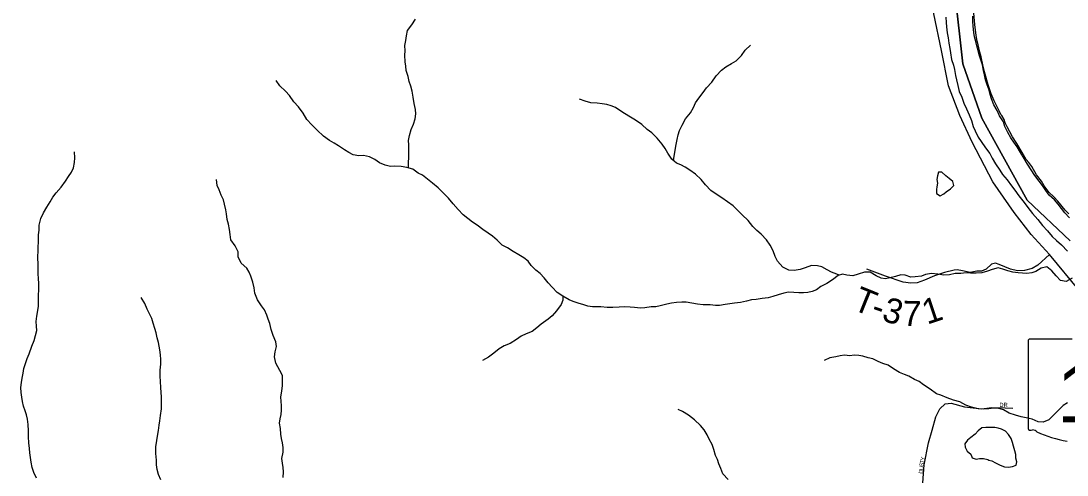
# Model space of a CAD drawing. Extents: x 1624196 to 2029251, y 146837 to 440034.
# Drawn here: x 1809621 to 1822196, y 296635 to 302092 of the extents above; entities that cross this region are included whole.
import ezdxf

# ---------------------------------------------------------------- set-up
doc = ezdxf.new("R2010")
doc.units = 0
for name, color, linetype in [('GM_X_Major_River', 7, 'Continuous'), ('GM_X_Minor_Lake', 7, 'Continuous'), ('GM_X_Minor_River', 7, 'Continuous'), ('GM_X_Section', 7, 'Continuous'), ('GM_X_State_Route', 7, 'Continuous'), ('GM_X_State_Shield', 7, 'Continuous'), ('GM_X_Township', 7, 'Continuous'), ('GM_X_Township_Road', 7, 'Continuous'), ('GM_X_Township_Road_Text', 7, 'Continuous'), ('GM_X_Township_Subdivision', 7, 'Continuous'), ('GM_X_Township_Subdivision_Text', 7, 'Continuous')]:
    doc.layers.add(name, color=color, linetype=linetype)

msp = doc.modelspace()

# ---------------------------------------------------------------- linework, layer by layer
at = {"layer": 'GM_X_Major_River'}
for points in [[(1820738, 302136), (1820741, 302073), (1820745, 302019), (1820754, 301949), (1820766, 301889), (1820776, 301824), (1820785, 301762), (1820795, 301710), (1820806, 301627), (1820832, 301559), (1820844, 301507), (1820855, 301438), (1820865, 301384), (1820881, 301316), (1820900, 301244), (1820930, 301175), (1820956, 301105), (1820987, 301034), (1821017, 300964), (1821045, 300896), (1821068, 300823), (1821090, 300771), (1821125, 300696), (1821161, 300642), (1821215, 300567), (1821267, 300499), (1821294, 300444), (1821336, 300376), (1821388, 300299), (1821420, 300247), (1821475, 300183), (1821529, 300112), (1821569, 300060), (1821617, 299989), (1821678, 299910), (1821724, 299848), (1821778, 299777), (1821846, 299707), (1821899, 299634), (1821959, 299568), (1822017, 299503), (1822067, 299453), (1822129, 299400), (1822202, 299325)], [(1822223, 299727), (1822169, 299785), (1822129, 299839), (1822090, 299892), (1822044, 299944), (1821980, 299999), (1821940, 300055), (1821900, 300114), (1821859, 300166), (1821809, 300233), (1821765, 300301), (1821719, 300372), (1821680, 300438), (1821634, 300509), (1821594, 300577), (1821557, 300636), (1821521, 300688), (1821483, 300750), (1821449, 300823), (1821430, 300879), (1821384, 300952), (1821354, 301016), (1821317, 301083), (1821289, 301157), (1821273, 301209), (1821260, 301259), (1821232, 301334), (1821214, 301386), (1821203, 301444), (1821191, 301497), (1821179, 301563), (1821162, 301613), (1821138, 301684), (1821126, 301736), (1821111, 301794), (1821097, 301844), (1821081, 301901), (1821076, 301953), (1821068, 302027), (1821062, 302087), (1821063, 302148)]]:
    msp.add_lwpolyline(points, dxfattribs=at)
at = {"layer": 'GM_X_Minor_Lake'}
for points in [[(1820666, 300275), (1820652, 300275), (1820638, 300231), (1820632, 300185), (1820637, 300143), (1820631, 300097), (1820625, 300065), (1820627, 300017), (1820671, 299992), (1820713, 300014), (1820744, 300037)], [(1820744, 300037), (1820794, 300076), (1820836, 300116), (1820822, 300162), (1820778, 300197), (1820738, 300231), (1820692, 300273), (1820666, 300275)], [(1821234, 297207), (1821218, 297207), (1821172, 297201), (1821125, 297167), (1821089, 297127), (1821038, 297086), (1820998, 297054), (1820966, 297012), (1820970, 296969), (1820993, 296923), (1821039, 296887), (1821055, 296841), (1821101, 296826), (1821144, 296832), (1821192, 296832), (1821244, 296820), (1821257, 296815)], [(1821257, 296815), (1821290, 296805), (1821336, 296783), (1821392, 296755), (1821442, 296734), (1821492, 296728), (1821539, 296738), (1821583, 296754), (1821593, 296794), (1821581, 296836), (1821580, 296884), (1821566, 296928), (1821552, 296983), (1821540, 297027), (1821524, 297075), (1821491, 297121), (1821455, 297164), (1821409, 297188), (1821366, 297200), (1821326, 297205), (1821286, 297207), (1821234, 297207)], [(1821300, 297207), (1821298, 297207)]]:
    msp.add_lwpolyline(points, dxfattribs=at)
at = {"layer": 'GM_X_Minor_River'}
for points in [[(1814281, 300325), (1814281, 300384), (1814284, 300460), (1814284, 300527), (1814282, 300601), (1814279, 300657), (1814293, 300717), (1814312, 300789), (1814338, 300853), (1814361, 300915), (1814367, 300976), (1814364, 301028), (1814346, 301100), (1814336, 301177), (1814323, 301247), (1814307, 301309), (1814289, 301365), (1814274, 301426), (1814252, 301498), (1814247, 301548), (1814241, 301601), (1814237, 301679), (1814238, 301731), (1814236, 301795), (1814247, 301855), (1814255, 301913), (1814269, 301976), (1814320, 302046), (1814365, 302112)], [(1817466, 300411), (1817471, 300465), (1817485, 300536), (1817494, 300588), (1817508, 300668), (1817519, 300724), (1817535, 300774), (1817568, 300838), (1817608, 300916), (1817669, 300988), (1817704, 301050), (1817730, 301108), (1817771, 301162), (1817823, 301232), (1817862, 301288), (1817924, 301354), (1817979, 301432), (1818040, 301500), (1818092, 301541), (1818163, 301579), (1818217, 301611), (1818282, 301677), (1818328, 301741), (1818389, 301802)], [(1816133, 298784), (1816067, 298828), (1816005, 298893), (1815960, 298943), (1815912, 299006), (1815862, 299058), (1815810, 299095), (1815752, 299153), (1815716, 299204), (1815664, 299244), (1815606, 299283), (1815536, 299321), (1815471, 299364), (1815405, 299398), (1815345, 299459), (1815291, 299507), (1815237, 299540), (1815173, 299586), (1815103, 299637), (1815049, 299675), (1814993, 299718), (1814937, 299762), (1814877, 299825), (1814818, 299893), (1814760, 299964), (1814710, 300016), (1814636, 300085), (1814566, 300144), (1814507, 300192), (1814447, 300237), (1814395, 300263), (1814331, 300310), (1814259, 300332), (1814192, 300341), (1814116, 300345), (1814064, 300343), (1814000, 300360), (1813932, 300388), (1813874, 300427), (1813810, 300459), (1813740, 300474), (1813681, 300470), (1813615, 300484), (1813561, 300511), (1813509, 300543), (1813437, 300592), (1813385, 300624), (1813329, 300657), (1813257, 300709), (1813182, 300778), (1813116, 300843), (1813058, 300909), (1813012, 300984), (1812959, 301058), (1812903, 301121), (1812849, 301195), (1812799, 301248), (1812734, 301310), (1812688, 301375)], [(1819457, 299037), (1819429, 299049), (1819365, 299073), (1819313, 299100), (1819249, 299136), (1819194, 299151), (1819122, 299153), (1819048, 299124), (1818987, 299104), (1818915, 299094), (1818853, 299095), (1818779, 299133), (1818713, 299204), (1818685, 299260), (1818662, 299328), (1818626, 299399), (1818582, 299463), (1818519, 299530), (1818467, 299572), (1818417, 299623), (1818363, 299694), (1818289, 299762), (1818233, 299817), (1818180, 299871), (1818114, 299920), (1818046, 299968), (1817978, 300009), (1817912, 300055), (1817850, 300122), (1817796, 300185), (1817728, 300251), (1817663, 300300), (1817603, 300336), (1817551, 300361), (1817500, 300383), (1817443, 300429), (1817395, 300504), (1817363, 300558), (1817327, 300611), (1817270, 300683), (1817206, 300746), (1817150, 300788), (1817086, 300847), (1817008, 300900), (1816948, 300934), (1816874, 300979), (1816820, 301017), (1816768, 301052), (1816716, 301070), (1816662, 301086), (1816606, 301097), (1816548, 301103), (1816472, 301108), (1816401, 301128), (1816333, 301153)], [(1809808, 296598), (1809777, 296664), (1809755, 296727), (1809745, 296789), (1809736, 296847), (1809728, 296902), (1809724, 296954), (1809715, 297024), (1809711, 297096), (1809710, 297167), (1809708, 297241), (1809698, 297307), (1809689, 297357), (1809671, 297408), (1809653, 297464), (1809640, 297520), (1809632, 297572), (1809624, 297629), (1809621, 297689), (1809627, 297747), (1809637, 297801), (1809646, 297859), (1809656, 297917), (1809675, 297975), (1809695, 298034), (1809720, 298092), (1809750, 298184), (1809779, 298250), (1809797, 298310), (1809810, 298372), (1809808, 298426), (1809805, 298482), (1809813, 298545), (1809823, 298613), (1809830, 298663), (1809832, 298723), (1809831, 298787), (1809835, 298867), (1809834, 298942), (1809830, 298992), (1809828, 299056), (1809827, 299106), (1809829, 299175), (1809824, 299243), (1809828, 299347), (1809833, 299467), (1809833, 299520), (1809838, 299576), (1809842, 299636), (1809859, 299716), (1809893, 299786), (1809934, 299854), (1809971, 299920), (1810003, 299974), (1810046, 300028), (1810104, 300096), (1810157, 300166), (1810191, 300222), (1810230, 300274), (1810252, 300326), (1810265, 300392), (1810267, 300446), (1810264, 300520)], [(1812773, 296607), (1812775, 296673), (1812774, 296725), (1812764, 296779), (1812756, 296833), (1812771, 296910), (1812771, 296966), (1812765, 297024), (1812754, 297076), (1812744, 297128), (1812739, 297193), (1812729, 297257), (1812735, 297311), (1812748, 297363), (1812754, 297415), (1812752, 297470), (1812747, 297520), (1812745, 297574), (1812756, 297644), (1812764, 297712), (1812764, 297762), (1812763, 297833), (1812733, 297893), (1812683, 297980), (1812670, 298054), (1812678, 298114), (1812691, 298178), (1812685, 298236), (1812652, 298311), (1812628, 298383), (1812612, 298458), (1812593, 298508), (1812575, 298558), (1812549, 298619), (1812511, 298669), (1812466, 298739), (1812434, 298822), (1812423, 298884), (1812409, 298954), (1812383, 299023), (1812366, 299073), (1812338, 299123), (1812270, 299180), (1812230, 299259), (1812231, 299319), (1812197, 299391), (1812143, 299462), (1812134, 299526), (1812126, 299584), (1812114, 299649), (1812101, 299705), (1812091, 299773), (1812083, 299823), (1812068, 299890), (1812054, 299944), (1812026, 300000), (1812003, 300063), (1811981, 300115), (1811973, 300185)], [(1822258, 299000), (1822184, 298960), (1822118, 298971), (1822064, 299027), (1822014, 299090), (1821952, 299138), (1821886, 299121), (1821821, 299079), (1821771, 299063), (1821711, 299057), (1821661, 299060), (1821608, 299064), (1821544, 299072), (1821482, 299087), (1821422, 299111), (1821366, 299126), (1821296, 299106), (1821241, 299086), (1821169, 299063), (1821101, 299059), (1821036, 299061), (1820984, 299064), (1820918, 299056), (1820850, 299056), (1820783, 299039), (1820713, 299035), (1820643, 299048), (1820567, 299056), (1820494, 299045), (1820444, 299025), (1820368, 299015), (1820318, 299014), (1820249, 299038), (1820199, 299040), (1820133, 299021), (1820065, 299003), (1820012, 298991), (1819962, 299002), (1819900, 299030), (1819828, 299073), (1819760, 299073), (1819686, 299049), (1819619, 299028), (1819547, 299038), (1819495, 299049), (1819443, 299033), (1819376, 298981), (1819307, 298937), (1819237, 298902), (1819182, 298862), (1819130, 298842), (1819080, 298828), (1819028, 298823), (1818973, 298823), (1818913, 298829), (1818847, 298834), (1818791, 298822), (1818724, 298800), (1818658, 298781), (1818604, 298765), (1818531, 298757), (1818459, 298746), (1818401, 298740), (1818341, 298724), (1818270, 298707), (1818198, 298701), (1818142, 298691), (1818087, 298684), (1818019, 298674), (1817969, 298672), (1817905, 298679), (1817822, 298681), (1817752, 298690), (1817616, 298711), (1817564, 298711), (1817501, 298709), (1817439, 298702), (1817383, 298690), (1817305, 298670), (1817254, 298657), (1817198, 298655), (1817120, 298645), (1817067, 298642), (1816995, 298648), (1816943, 298652), (1816881, 298655), (1816811, 298653), (1816734, 298650), (1816666, 298650), (1816592, 298655), (1816540, 298657), (1816490, 298657), (1816437, 298666), (1816387, 298680), (1816317, 298702), (1816259, 298721), (1816209, 298741), (1816133, 298784)], [(1816133, 298784), (1816133, 298738), (1816114, 298684), (1816058, 298608), (1816007, 298550), (1815957, 298510), (1815874, 298448), (1815821, 298404), (1815767, 298359), (1815695, 298333), (1815632, 298305), (1815576, 298263), (1815503, 298214), (1815429, 298186), (1815370, 298152), (1815304, 298098), (1815241, 298053), (1815167, 298011)], [(1811303, 296577), (1811276, 296642), (1811258, 296702), (1811250, 296756), (1811249, 296814), (1811243, 296895), (1811242, 296975), (1811254, 297051), (1811263, 297101), (1811273, 297169), (1811282, 297233), (1811290, 297288), (1811300, 297352), (1811311, 297430), (1811309, 297494), (1811312, 297572), (1811306, 297633), (1811301, 297685), (1811297, 297765), (1811294, 297821), (1811296, 297896), (1811303, 297968), (1811303, 298022), (1811299, 298080), (1811290, 298138), (1811274, 298227), (1811260, 298283), (1811245, 298343), (1811229, 298398), (1811209, 298462), (1811194, 298518), (1811164, 298579), (1811138, 298629), (1811111, 298695), (1811067, 298768)], [(1822200, 297503), (1822150, 297469), (1821976, 297298), (1821910, 297272), (1821848, 297273), (1821775, 297307), (1821703, 297324), (1821645, 297334), (1821575, 297353), (1821501, 297379), (1821433, 297418), (1821365, 297438), (1821311, 297438), (1821256, 297431), (1821194, 297425), (1821128, 297431), (1821046, 297452), (1820978, 297476), (1820906, 297513), (1820832, 297536), (1820754, 297562), (1820679, 297593), (1820627, 297613), (1820551, 297666), (1820470, 297720), (1820416, 297761), (1820360, 297785), (1820292, 297822), (1820240, 297844), (1820181, 297867), (1820110, 297911), (1820044, 297954), (1819979, 297976), (1819925, 297999), (1819859, 298033), (1819803, 298045), (1819741, 298062), (1819691, 298072), (1819637, 298074), (1819585, 298069), (1819521, 298077), (1819468, 298069), (1819416, 298054), (1819344, 298044), (1819275, 298012)], [(1818120, 296581), (1818056, 296651), (1818034, 296712), (1818011, 296770), (1817993, 296822), (1817971, 296872), (1817949, 296943), (1817928, 297001), (1817892, 297068), (1817868, 297120), (1817833, 297178), (1817791, 297231), (1817717, 297297), (1817645, 297354), (1817573, 297397), (1817519, 297421)]]:
    msp.add_lwpolyline(points, dxfattribs=at)
at = {"layer": 'GM_X_Section'}
msp.add_lwpolyline([(1822218, 299773), (1822173, 299819), (1822085, 299928), (1822036, 299980), (1821980, 300032), (1821922, 300111), (1821887, 300165), (1821829, 300241), (1821770, 300344), (1821734, 300392), (1821704, 300428), (1821655, 300510), (1821593, 300619), (1821540, 300699), (1821475, 300818), (1821453, 300866), (1821439, 300906), (1821410, 300954), (1821398, 300968), (1821380, 301010), (1821321, 301133), (1821283, 301215), (1821248, 301323), (1821203, 301479), (1821183, 301565), (1821164, 301660), (1821148, 301716), (1821135, 301768), (1821127, 301806), (1821113, 301848), (1821101, 301916), (1821086, 302050), (1821075, 302184)], dxfattribs=at)
at = {"layer": 'GM_X_State_Route'}
msp.add_lwpolyline([(1822349, 298845), (1821983, 299287), (1821762, 299525), (1821559, 299791), (1821303, 300158), (1821053, 300635), (1820907, 300954), (1820772, 301312), (1820688, 301736), (1820594, 302178), (1820512, 302602), (1820474, 302809), (1820440, 303187), (1820411, 303644), (1820411, 303650)], dxfattribs=at)
at = {"layer": 'GM_X_State_Shield'}
for p, q in [((1821729, 298250), (1821729, 297193)), ((1822256, 298268), (1821746, 298268))]:
    msp.add_line(p, q, dxfattribs=at)
for centre, major_axis, start_param, end_param in [((1821749, 298252), (20.2, 0), 1.712693, 3.28349), ((1821749, 297191), (20.3, 0), 3.00124, 4.508301), ((1821753, 297299), (155, 0), 4.665946, 4.897461), ((1821784, 297132), (56, 0), 0.519207, 1.627899), ((1822491, 298081), (1333, 0), 4.195997, 4.488961)]:
    msp.add_ellipse(centre, major_axis=major_axis, ratio=0.8, start_param=start_param, end_param=end_param, dxfattribs=at)
at = {"layer": 'GM_X_Township'}
for points in [[(1822496, 306522), (1821987, 306056), (1821498, 305265), (1821140, 304614), (1820879, 304196), (1820737, 303940), (1820824, 302920), (1820846, 302443), (1820943, 301575), (1821171, 300924), (1821714, 299937), (1822234, 299449)], [(1822234, 299449), (1821714, 299937), (1821171, 300924), (1820943, 301575), (1820846, 302443), (1820824, 302920), (1820737, 303940), (1820879, 304196), (1826068, 304023)]]:
    msp.add_lwpolyline(points, dxfattribs=at)
at = {"layer": 'GM_X_Township_Road'}
msp.add_lwpolyline([(1821983, 299287), (1821843, 299157), (1821776, 299116), (1821683, 299092), (1821598, 299088), (1821517, 299109), (1821381, 299164), (1821336, 299180), (1821286, 299171), (1821224, 299107), (1821165, 299085), (1821110, 299084), (1821030, 299067), (1820937, 299090), (1820873, 299101), (1820837, 299097), (1820722, 299070), (1820602, 299029), (1820482, 298975), (1820392, 298946), (1820317, 298939), (1820227, 298952), (1820013, 299023), (1819789, 299111)], dxfattribs=at)
at = {"layer": 'GM_X_Township_Subdivision'}
msp.add_lwpolyline([(1820462, 296540), (1820478, 296756), (1820528, 297023), (1820572, 297173), (1820618, 297334), (1820665, 297429), (1820730, 297490), (1820802, 297499), (1820964, 297456), (1821169, 297431), (1821286, 297447), (1821452, 297443), (1821545, 297440)], dxfattribs=at)

# ---------------------------------------------------------------- texts
at = {"layer": 'GM_X_State_Shield'}
msp.add_text('104', height=696.1, dxfattribs=at).set_placement((1822075, 297267))
at = {"layer": 'GM_X_Township_Road_Text'}
for s, rotation, p in [('T', 338.1532, (1819602, 298630)), ('-', 340.3908, (1819822, 298542)), ('3', 343.5573, (1819955, 298495)), ('7', 358.4016, (1820216, 298430)), ('1', 18.3679, (1820513, 298441))]:
    msp.add_text(s, height=300, rotation=rotation, dxfattribs=at).set_placement(p)
at = {"layer": 'GM_X_Township_Subdivision_Text'}
for s, rotation, p in [('DR', 0, (1821382, 297454)), ('S', 82.6039, (1820469, 296736)), ('T', 79.9762, (1820474, 296771)), ('Y', 79.7147, (1820480, 296805)), ('D', 85.1637, (1820462, 296649)), ('U', 85.1637, (1820466, 296693))]:
    msp.add_text(s, height=50, rotation=rotation, dxfattribs=at).set_placement(p)

doc.saveas('drawing.dxf')
